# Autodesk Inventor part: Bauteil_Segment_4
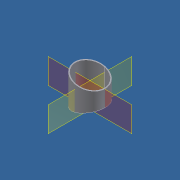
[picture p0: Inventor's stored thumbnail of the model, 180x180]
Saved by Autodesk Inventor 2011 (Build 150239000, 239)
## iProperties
Created: 2009-03
Part Number: Bauteil_Segment_4
Material: S235JR
Document SubType Name: Blech
Designer: Guido Walteich
Density: 7.86 g/cm^3
Flat Pattern Width: 49.112 cm
Flat Pattern Length: 9.54779 cm
Flat Pattern Area: 468.911 cm^2
Description: Blech
Mass: 738.822 g
Surface Area: 660.584 cm^2
Volume: 93.9977 cm^3
Sheet Metal Rule: Standard_mm
Stärke: 3 mm
d0: 160 mm
d6: 95 mm
Gestr_Neutral: 491 mm
Maße: = Ø<d0> x L=<d6> , aus Blech <Stärke> x <d6> x <Gestr_neutral>
Author: Guido Walteich
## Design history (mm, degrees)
node "Skizze1"
node "Konturlasche1"
  sketch "Skizze2"
    geometry: L1 (-98, 0)-(98, 0) reference; L2 (0, -98.1)-(0, 98.6) reference; A1 r 80 centre (0, 0) between (-0.5, 79.998) and (0.5, 79.998); A2 r 0.5 centre (0, 80) between (0.5, 79.998) and (-0.5, 79.998)
    constraints: 5 point on circle, 2 centre point, 2 point on line, 1 midpoint
    dimensions: "d0" = 160 diameter of A1 (= Rohr_D); "d1" = 1 diameter of A2
workplane "Arbeitsebene1"
workplane "Arbeitsebene2"
sketch "Skizze6"
  geometry: L1 (80, 0)-(80, 95.478) reference; L2 (-80, 0)-(-80, 95.478) reference; L3 (-80, 95.478)-(80, 95.478) reference; L4 (80, 0)-(-80, 0) reference; L5 (-80, 31.826)-(80, 0); L6 (80, 95.478)-(-80, 63.652); 4 further points
  constraints: 4 end point, 2 point on line
  dimensions: "d21" = 11.25 deg angle of L5 L4 (= WINKEL); "d24" = 11.25 deg angle of L3 L6 (= WINKEL)
extrude "Extrusion2" cut sketch "Skizze6" stored distance "d25" = 320 (= 2 x Rohr_D); taper "d26" = 0 deg
node "Volumenkörper1"
feature "Grobblech1" dims "d2" = 3 (= BreiteBiegungsfreistellung), "d3" = 1.5 (= TiefeBiegungsfreistellung), "d4" = 6 (= MinimalRest), "d5" = 3 (= Biegeradius), "d6" = 95.47792 (= Länge_4), "d7" = 3 (= Biegeradius), "d8" = 3 (= Wandstärke), "d9" = 12 (= GrößeEckenfreistellung), "d10" = 3 (= Stärke), "d11" = 3 (= JacobiRadiusGröße), "Stärke" = 3 (= Wandstärke), "AbstandVerbindung" = 0.01
feature "Biegung1" dims "d2" = 3 (= BreiteBiegungsfreistellung), "d3" = 1.5 (= TiefeBiegungsfreistellung), "d4" = 6 (= MinimalRest), "d5" = 3 (= Biegeradius), "d7" = 3 (= Biegeradius), "d8" = 3 (= Wandstärke), "Stärke" = 3 (= Wandstärke), "AbstandVerbindung" = 0.01
feature "Ecke1" dims "d8" = 3 (= Wandstärke), "d9" = 12 (= GrößeEckenfreistellung), "d10" = 3 (= Stärke), "d11" = 3 (= JacobiRadiusGröße)
feature "Definition1"
other parameters: "KFaktor" = 4.4, "Biegeradius" = 3 (= Stärke), "BreiteBiegungsfreistellung" = 3 (= Stärke), "TiefeBiegungsfreistellung" = 1.5 (= 0.5 x Stärke), "GrößeEckenfreistellung" = 12 (= 4 x Stärke), "MinimalRest" = 6 (= 2 x Stärke), "Übergangsradius" = 3 (= Biegeradius), "JacobiRadiusGröße" = 3 (= Biegeradius), "Rohr_D" = 160 [user parameter; used in 3 equation terms], "WINKEL_3" = 1.9635 [user parameter], "WINKEL_4" = 1.9635 [user parameter], "Länge_4" = 95.47792 [user parameter; used in 1 equation term], "Wandstärke" = 3 [user parameter; used in 3 equation terms], "d12" = 0, "d13" = 0, "Gestr_Neutral" = 490.87375 (computed from Rohr_D, Wandstärke) [user parameter], "WINKEL" = 11.25 deg [user parameter; used in 2 equation terms], "Länge_1" = 47.73896 [user parameter], "Länge_2" = 95.47792 [user parameter], "Länge_3" = 95.47792 [user parameter], "Länge_5" = 47.73896 [user parameter], "ANZ_TEILE" = 39.78874 [user parameter], "GES_WINKEL" = 90 deg [user parameter], "Abstandsgröße" = 3 (= Stärke), "Gestr_Neutral" = 490.87375, "Länge_4" = 95.47792, "WINKEL_3" = 1.9635, "WINKEL_4" = 1.9635, "Wandstärke" = 3, "Biegeradius" = 3, "BreiteBiegungsfreistellung" = 3, "GrößeEckenfreistellung" = 12, "JacobiRadiusGröße" = 3, "MinimalRest" = 6, "Stärke" = 3, "TiefeBiegungsfreistellung" = 1.5, "Übergangsradius" = 3, "WINKEL" = 1.9635, "ANZ_TEILE" = 39.78874, "GES_WINKEL" = 90 deg, "Länge_1" = 47.73896, "Länge_2" = 95.47792, "Länge_3" = 95.47792, "Länge_5" = 47.73896, "Abstandsgröße" = 3
